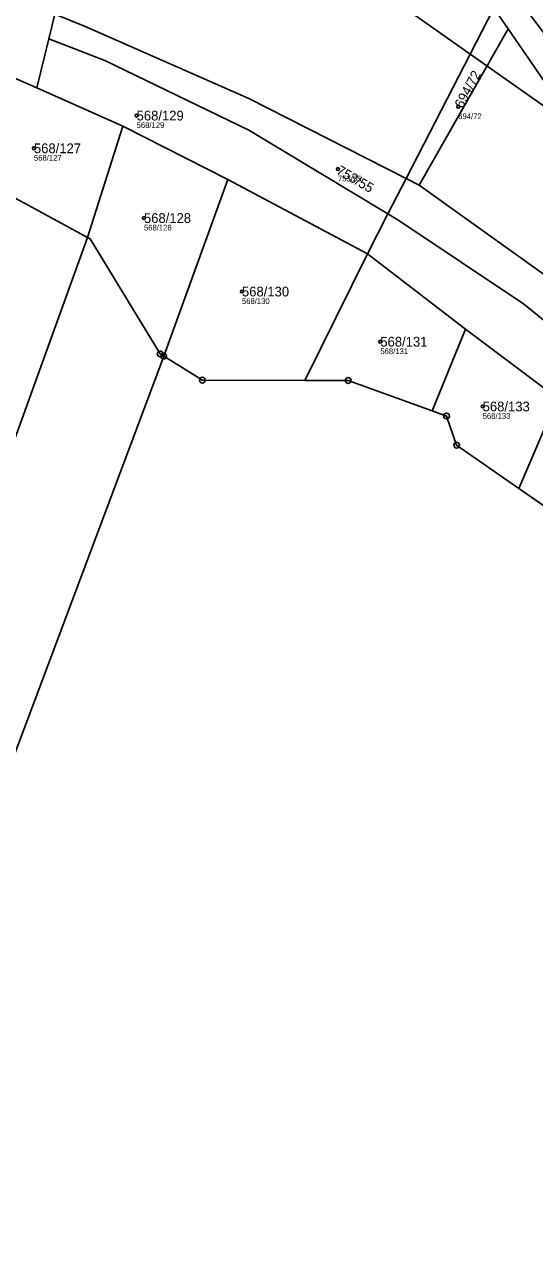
# Model space of a CAD drawing. Extents: x -732749 to -730903, y -1025757 to -1023435.
# Drawn here: x -731373.8 to -731284.8, y -1024442.6 to -1024229.5 of the extents above; entities that cross this region are included whole.
import ezdxf

# ---------------------------------------------------------------- set-up
doc = ezdxf.new("R2010")
doc.units = 0
for name, color, linetype in [('Definiční body', 7, 'Continuous'), ('Hranice parcel', 7, 'Continuous'), ('Parcelní čísla', 7, 'Continuous'), ('Polygon parcely', 7, 'Continuous'), ('Poz předměty', 7, 'Continuous'), ('Značky bodu BP', 7, 'Continuous')]:
    doc.layers.add(name, color=color, linetype=linetype)

msp = doc.modelspace()

# ---------------------------------------------------------------- linework, layer by layer
at = {"layer": 'Definiční body'}
for centre in [(-731298.1, -1024243.9), (-731354.19, -1024245.44), (-731372.1, -1024251.15), (-731319.08, -1024254.76), (-731352.91, -1024263.32), (-731335.82, -1024276.14), (-731311.69, -1024284.89), (-731293.84, -1024296.19)]:
    msp.add_circle(centre, 0.25, dxfattribs=at)
at = {"layer": 'Hranice parcel'}
for p, q in [((-731307.2, -1024256.43), (-731291.89, -1024226.68)), ((-731291.89, -1024226.68), (-731289.39, -1024230.29)), ((-731369.52, -1024232.06), (-731368.48, -1024227.77)), ((-731368.48, -1024227.77), (-731363.3, -1024229.86)), ((-731289.39, -1024230.29), (-731304.91, -1024257.6)), ((-731371.6, -1024240.62), (-731369.52, -1024232.06)), ((-731359.71, -1024235.81), (-731369.52, -1024232.06)), ((-731376.76, -1024238.32), (-731371.6, -1024240.62)), ((-731356.62, -1024247.28), (-731371.6, -1024240.62)), ((-731362.74, -1024266.71), (-731356.62, -1024247.28)), ((-731338.29, -1024256.61), (-731356.62, -1024247.28)), ((-731349.47, -1024287.4), (-731338.29, -1024256.61)), ((-731338.29, -1024256.61), (-731313.95, -1024269.54)), ((-731310.37, -1024262.58), (-731307.2, -1024256.43)), ((-731307.2, -1024256.43), (-731304.91, -1024257.6)), ((-731313.95, -1024269.54), (-731310.37, -1024262.58)), ((-731324.84, -1024291.64), (-731313.95, -1024269.54)), ((-731302.67, -1024296.93), (-731296.83, -1024282.7)), ((-731280.81, -1024294.75), (-731296.83, -1024282.7)), ((-731287.55, -1024310.47), (-731280.81, -1024294.75)), ((-731273.03, -1024320.55), (-731287.55, -1024310.47))]:
    msp.add_line(p, q, dxfattribs=at)
for points in [[(-731363.3, -1024229.86), (-731334.65, -1024242.43), (-731307.2, -1024256.43)], [(-731289.39, -1024230.29), (-731254.49, -1024281.1), (-731233.27, -1024301.79), (-731226.03, -1024310.36)], [(-731310.37, -1024262.58), (-731334.62, -1024247.99), (-731359.71, -1024235.81)], [(-731362.74, -1024266.71), (-731379.17, -1024257.79), (-731382.65, -1024255.67)], [(-731304.91, -1024257.6), (-731282.64, -1024273.5), (-731260.25, -1024288.87), (-731237.16, -1024306.6), (-731228.37, -1024314.75)], [(-731232.57, -1024323.26), (-731243.94, -1024311.77), (-731265.19, -1024295.67), (-731286.7, -1024278.29), (-731308.48, -1024263.72), (-731310.37, -1024262.58)], [(-731362.74, -1024266.71), (-731402.33, -1024376.24), (-731413.53, -1024420.89), (-731422.57, -1024470.76), (-731425.03, -1024531.86), (-731448.91, -1024627.9)], [(-731349.47, -1024287.4), (-731350.09, -1024287.01), (-731362.28, -1024266.96), (-731362.74, -1024266.71)], [(-731296.83, -1024282.7), (-731297.06, -1024282.52), (-731313.95, -1024269.54)], [(-731349.47, -1024287.4), (-731384.29, -1024380.16), (-731396.92, -1024430.73), (-731405.68, -1024487.75), (-731408.32, -1024539.25), (-731411.17, -1024556.07), (-731428.58, -1024623.59)], [(-731324.84, -1024291.64), (-731342.73, -1024291.6), (-731349.47, -1024287.4)], [(-731302.67, -1024296.93), (-731317.3, -1024291.65), (-731324.84, -1024291.64)], [(-731287.55, -1024310.47), (-731298.38, -1024302.94), (-731300.13, -1024297.85), (-731302.67, -1024296.93)]]:
    msp.add_lwpolyline(points, dxfattribs=at)
at = {"layer": 'Polygon parcely'}
for points in [[(-731352.8, -1024162.42), (-731362.05, -1024199.67), (-731368.48, -1024227.77), (-731363.3, -1024229.86), (-731334.65, -1024242.43), (-731307.2, -1024256.43), (-731291.89, -1024226.68), (-731327.65, -1024175.13)], [(-731385.1, -1024221.06), (-731386.22, -1024225.67), (-731388.07, -1024233.27), (-731376.76, -1024238.32), (-731371.6, -1024240.62), (-731369.52, -1024232.06), (-731368.48, -1024227.77)], [(-731223.73, -1024306.06), (-731261.69, -1024259.33), (-731289.7, -1024222.41), (-731291.89, -1024226.68), (-731289.39, -1024230.29), (-731254.49, -1024281.1), (-731233.27, -1024301.79), (-731226.03, -1024310.36)], [(-731304.91, -1024257.6), (-731289.39, -1024230.29), (-731291.89, -1024226.68), (-731307.2, -1024256.43)], [(-731310.37, -1024262.58), (-731307.2, -1024256.43), (-731334.65, -1024242.43), (-731363.3, -1024229.86), (-731368.48, -1024227.77), (-731369.52, -1024232.06), (-731359.71, -1024235.81), (-731334.62, -1024247.99)], [(-731289.39, -1024230.29), (-731304.91, -1024257.6), (-731282.64, -1024273.5), (-731260.25, -1024288.87), (-731237.16, -1024306.6), (-731228.37, -1024314.75), (-731226.03, -1024310.36), (-731233.27, -1024301.79), (-731254.49, -1024281.1)], [(-731310.37, -1024262.58), (-731334.62, -1024247.99), (-731359.71, -1024235.81), (-731369.52, -1024232.06), (-731371.6, -1024240.62), (-731356.62, -1024247.28), (-731338.29, -1024256.61), (-731313.95, -1024269.54)], [(-731356.62, -1024247.28), (-731371.6, -1024240.62), (-731376.76, -1024238.32), (-731382.65, -1024255.67), (-731379.17, -1024257.79), (-731362.74, -1024266.71)], [(-731447.72, -1024401.19), (-731456.94, -1024445.25), (-731461.16, -1024506.28), (-731488.88, -1024628.34), (-731492.81, -1024644.46), (-731472.2, -1024634.49), (-731466.1, -1024631.54), (-731448.91, -1024627.9), (-731425.03, -1024531.86), (-731422.57, -1024470.76), (-731413.53, -1024420.89), (-731402.33, -1024376.24), (-731362.74, -1024266.71), (-731379.17, -1024257.79), (-731382.65, -1024255.67), (-731400.22, -1024244.97), (-731439.11, -1024360.74)], [(-731349.47, -1024287.4), (-731338.29, -1024256.61), (-731356.62, -1024247.28), (-731362.74, -1024266.71), (-731362.28, -1024266.96), (-731350.09, -1024287.01)], [(-731324.84, -1024291.64), (-731313.95, -1024269.54), (-731338.29, -1024256.61), (-731349.47, -1024287.4), (-731342.73, -1024291.6)], [(-731230.9, -1024319.49), (-731228.37, -1024314.75), (-731237.16, -1024306.6), (-731260.25, -1024288.87), (-731282.64, -1024273.5), (-731304.91, -1024257.6), (-731307.2, -1024256.43), (-731310.37, -1024262.58), (-731308.48, -1024263.72), (-731286.7, -1024278.29), (-731265.19, -1024295.67), (-731243.94, -1024311.77), (-731232.57, -1024323.26)], [(-731308.48, -1024263.72), (-731310.37, -1024262.58), (-731313.95, -1024269.54), (-731297.06, -1024282.52), (-731296.83, -1024282.7), (-731280.81, -1024294.75), (-731267.11, -1024305.06), (-731252.84, -1024316.03), (-731235.68, -1024330.27), (-731232.57, -1024323.26), (-731243.94, -1024311.77), (-731265.19, -1024295.67), (-731286.7, -1024278.29)], [(-731350.09, -1024287.01), (-731362.28, -1024266.96), (-731362.74, -1024266.71), (-731402.33, -1024376.24), (-731413.53, -1024420.89), (-731422.57, -1024470.76), (-731425.03, -1024531.86), (-731448.91, -1024627.9), (-731428.58, -1024623.59), (-731411.17, -1024556.07), (-731408.32, -1024539.25), (-731405.68, -1024487.75), (-731396.92, -1024430.73), (-731384.29, -1024380.16), (-731349.47, -1024287.4)], [(-731296.83, -1024282.7), (-731297.06, -1024282.52), (-731313.95, -1024269.54), (-731324.84, -1024291.64), (-731317.3, -1024291.65), (-731302.67, -1024296.93)], [(-731280.81, -1024294.75), (-731296.83, -1024282.7), (-731302.67, -1024296.93), (-731300.13, -1024297.85), (-731298.38, -1024302.94), (-731287.55, -1024310.47)], [(-731267.11, -1024305.06), (-731280.81, -1024294.75), (-731287.55, -1024310.47), (-731273.03, -1024320.55)]]:
    msp.add_lwpolyline(points, close=True, dxfattribs=at)
msp.add_lwpolyline([(-731174.6, -1024503.96), (-731158.69, -1024424.65), (-731149.46, -1024393.15), (-731161.12, -1024388.35), (-731168.19, -1024384.86), (-731188.01, -1024375.09), (-731196.85, -1024370.73), (-731205.11, -1024368.19), (-731225.02, -1024362.07), (-731236.29, -1024349.77), (-731241.55, -1024345.52), (-731258.62, -1024331.73), (-731268.94, -1024323.39), (-731273.03, -1024320.55), (-731287.55, -1024310.47), (-731298.38, -1024302.94), (-731300.13, -1024297.85), (-731302.67, -1024296.93), (-731317.3, -1024291.65), (-731324.84, -1024291.64), (-731342.73, -1024291.6), (-731349.47, -1024287.4), (-731384.29, -1024380.16)], dxfattribs=at)
at = {"layer": 'Poz předměty'}
msp.add_line((-731341.53, -1024202.62), (-731273.35, -1024250.7), dxfattribs=at)
at = {"layer": 'Značky bodu BP'}
for centre, radius in [((-731350.09, -1024287.01), 0.5), ((-731350.09, -1024287.01), 0.0303), ((-731349.47, -1024287.4), 0.5), ((-731349.47, -1024287.4), 0.0303), ((-731342.73, -1024291.6), 0.5), ((-731342.73, -1024291.6), 0.0303), ((-731317.3, -1024291.65), 0.5), ((-731317.3, -1024291.65), 0.0303), ((-731300.13, -1024297.85), 0.5), ((-731300.13, -1024297.85), 0.0303), ((-731298.38, -1024302.94), 0.5), ((-731298.38, -1024302.94), 0.0303)]:
    msp.add_circle(centre, radius, dxfattribs=at)

# ---------------------------------------------------------------- texts
at = {"layer": 'Definiční body'}
for s, p in [('568/129', (-731354.19, -1024247.6)), ('694/72', (-731298.1, -1024246.06)), ('568/127', (-731372.1, -1024253.31)), ('753/55', (-731319.08, -1024256.92)), ('568/128', (-731352.91, -1024265.48)), ('568/130', (-731335.82, -1024278.3)), ('568/131', (-731311.69, -1024287.05)), ('568/133', (-731293.84, -1024298.35))]:
    msp.add_text(s, height=1, dxfattribs=at).set_placement(p)
at = {"layer": 'Parcelní čísla'}
for s, rotation, p in [('694/72', 62, (-731297.35, -1024244.3)), ('753/55', 330, (-731319.51, -1024255.5))]:
    msp.add_text(s, height=1.7, rotation=rotation, dxfattribs=at).set_placement(p)
for s, p in [('568/129', (-731354.19, -1024246.29)), ('568/127', (-731372.1, -1024252)), ('568/128', (-731352.91, -1024264.17)), ('568/130', (-731335.82, -1024276.99)), ('568/131', (-731311.69, -1024285.74)), ('568/133', (-731293.84, -1024297.04))]:
    msp.add_text(s, height=1.7, dxfattribs=at).set_placement(p)

doc.saveas('drawing.dxf')
